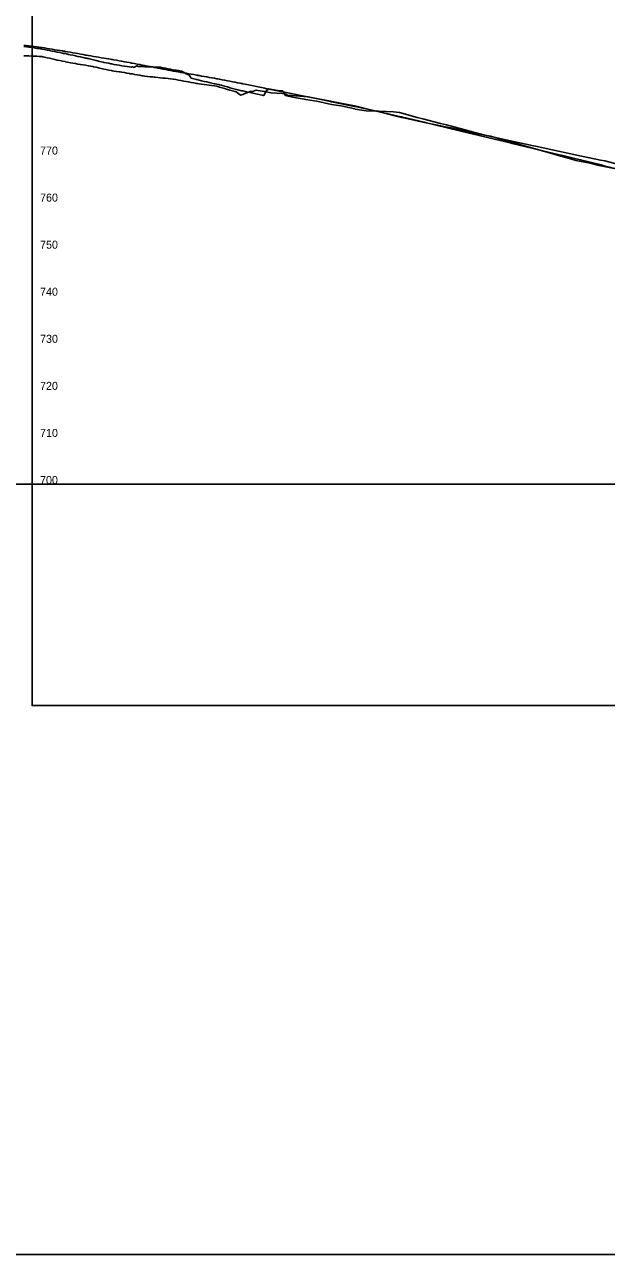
# Model space of a CAD drawing. Extents: x 1935020 to 1938620, y 1201670 to 1203870.
# Drawn here: x 1936228 to 1936846, y 1201670 to 1202977 of the extents above; entities that cross this region are included whole.
import ezdxf

# ---------------------------------------------------------------- set-up
doc = ezdxf.new("R2010")
doc.units = 0
for name, color, linetype in [('BR_EXIST_GROUND_LT', 7, 'Continuous'), ('BR_EXIST_GROUND_RT', 7, 'Continuous'), ('RD_DDB_ElevTX', 7, 'Continuous'), ('RD_DDB_Profile_EX', 7, 'Continuous'), ('RD_GPK_Profile_Cell', 7, 'Continuous'), ('RD_SHT_IplotShp', 7, 'Continuous'), ('RD_SHT_ShtClip', 7, 'Continuous')]:
    doc.layers.add(name, color=color, linetype=linetype)

msp = doc.modelspace()

# ---------------------------------------------------------------- linework, layer by layer
at = {"layer": 'BR_EXIST_GROUND_LT'}
msp.add_lwpolyline([(1936226.8, 1202943.8), (1936229.5, 1202943.7), (1936232.2, 1202943.5), (1936235, 1202943.4), (1936237.7, 1202943.3), (1936240.4, 1202943.2), (1936243.2, 1202943.1), (1936245.4, 1202943), (1936245.9, 1202942.9), (1936246.9, 1202942.7), (1936248.6, 1202942.3), (1936251.4, 1202941.6), (1936254.1, 1202941), (1936256.9, 1202940.4), (1936259.6, 1202939.8), (1936262.3, 1202939.2), (1936265.1, 1202938.6), (1936267.8, 1202938), (1936270.5, 1202937.5), (1936270.9, 1202937.4), (1936273.3, 1202936.9), (1936276.2, 1202936.3), (1936278.7, 1202935.9), (1936281.5, 1202935.4), (1936284.2, 1202934.9), (1936286.9, 1202934.4), (1936289.7, 1202934), (1936292.4, 1202933.6), (1936295.2, 1202933.1), (1936297.9, 1202932.6), (1936300.2, 1202932.2), (1936300.6, 1202932.1), (1936303.4, 1202931.5), (1936306.1, 1202930.8), (1936308.8, 1202930.2), (1936311.6, 1202929.6), (1936314.3, 1202929), (1936317, 1202928.5), (1936319.8, 1202927.9), (1936320.6, 1202927.7), (1936322.5, 1202927.5), (1936325.2, 1202927.1), (1936328, 1202926.7), (1936329.2, 1202926.6), (1936330.7, 1202926.3), (1936333.5, 1202925.8), (1936336.2, 1202925.3), (1936338.9, 1202924.8), (1936339.7, 1202924.7), (1936341.7, 1202924.4), (1936344.4, 1202923.9), (1936347.1, 1202923.4), (1936349.9, 1202923), (1936352.6, 1202922.5), (1936353.6, 1202922.3), (1936355.3, 1202922.1), (1936358.1, 1202921.8), (1936360.8, 1202921.5), (1936363.5, 1202921.2), (1936365.2, 1202921), (1936366.3, 1202920.9), (1936369, 1202920.7), (1936371.7, 1202920.4), (1936374.5, 1202920.1), (1936375.9, 1202920), (1936377.2, 1202919.9), (1936380, 1202919.5), (1936382.7, 1202919.2), (1936385.4, 1202918.9), (1936385.7, 1202918.9), (1936388.2, 1202918.4), (1936390.9, 1202917.9), (1936393.6, 1202917.4), (1936396.4, 1202916.9), (1936399.1, 1202916.4), (1936401.4, 1202916.1), (1936401.8, 1202916), (1936404.6, 1202915.4), (1936407.3, 1202914.9), (1936410, 1202914.4), (1936411.3, 1202914.1), (1936412.8, 1202913.9), (1936415.5, 1202913.5), (1936418.3, 1202913.2), (1936421, 1202912.8), (1936423.7, 1202912.5), (1936426, 1202912.2), (1936426.5, 1202912.1), (1936429.2, 1202911.7), (1936431.9, 1202911.3), (1936434.7, 1202910.4), (1936437.4, 1202909.6), (1936440.1, 1202908.8), (1936440.9, 1202908.5), (1936442.9, 1202908), (1936445.6, 1202907.3), (1936448.3, 1202906.6), (1936451.1, 1202905.9), (1936452.4, 1202905.5), (1936453.8, 1202904.4), (1936456.6, 1202902.1), (1936457, 1202901.7), (1936459.3, 1202902.6), (1936460.8, 1202903.2), (1936462, 1202903.7), (1936467.2, 1202905.8), (1936469.6, 1202905.8), (1936473.6, 1202907.2), (1936475.2, 1202906.9), (1936482.3, 1202905.6), (1936489.6, 1202904.3), (1936501.1, 1202903.6), (1936502.9, 1202903.4), (1936503.8, 1202903.2), (1936506.9, 1202902), (1936528.4, 1202900.1), (1936552.6, 1202895.5), (1936553.3, 1202895.3), (1936553.9, 1202895.3), (1936577.8, 1202890.7), (1936578.2, 1202890.6), (1936600.8, 1202884.9), (1936602.7, 1202884.4), (1936604, 1202884.2), (1936628, 1202878.2), (1936628.6, 1202878.1), (1936652.3, 1202872.9), (1936676.4, 1202867.7), (1936679, 1202867.2), (1936680.6, 1202867), (1936704.2, 1202861.9), (1936719.6, 1202858.5), (1936743.8, 1202853.3), (1936768.2, 1202848), (1936770.3, 1202847.6), (1936794.8, 1202842.3), (1936814.2, 1202838.1), (1936839.1, 1202832.9), (1936843.7, 1202832), (1936862.4, 1202827.2)], dxfattribs=at)
at = {"layer": 'BR_EXIST_GROUND_RT'}
msp.add_lwpolyline([(1936226.8, 1202953.5), (1936229.5, 1202953.1), (1936232.2, 1202952.8), (1936235, 1202952.4), (1936237.7, 1202952), (1936240.4, 1202951.6), (1936240.9, 1202951.6), (1936243.2, 1202951.3), (1936244.5, 1202951.1), (1936245.9, 1202950.8), (1936248.6, 1202950.3), (1936251.4, 1202949.8), (1936254.1, 1202949.2), (1936256.9, 1202948.7), (1936259.6, 1202948.2), (1936262.3, 1202947.6), (1936265.1, 1202947.1), (1936267.8, 1202946.5), (1936268.9, 1202946.3), (1936270.5, 1202946), (1936273.3, 1202945.4), (1936274.2, 1202945.2), (1936276, 1202944.8), (1936278.7, 1202944.3), (1936281.5, 1202943.7), (1936284.2, 1202943.1), (1936286.9, 1202942.5), (1936289.7, 1202941.9), (1936292.4, 1202941.3), (1936293.5, 1202941.1), (1936294.5, 1202940.9), (1936295.2, 1202940.7), (1936296.2, 1202940.5), (1936297.9, 1202940.1), (1936300.6, 1202939.4), (1936303.4, 1202938.7), (1936306.1, 1202938.1), (1936308.8, 1202937.4), (1936310.9, 1202936.8), (1936311.6, 1202936.7), (1936314.3, 1202936.2), (1936317, 1202935.7), (1936319, 1202935.3), (1936319.8, 1202935.1), (1936322.5, 1202934.6), (1936325.2, 1202934.2), (1936328, 1202933.7), (1936330.7, 1202933.2), (1936333.5, 1202932.8), (1936336.2, 1202932.4), (1936336.6, 1202932.3), (1936338.9, 1202932), (1936341, 1202931.7), (1936341.7, 1202931.9), (1936342.2, 1202932.1), (1936343.8, 1202931.3), (1936344.4, 1202931.7), (1936346.6, 1202933.2), (1936347.1, 1202933), (1936348.3, 1202932.4), (1936349.9, 1202932.4), (1936352.6, 1202932.3), (1936355.3, 1202932.1), (1936358.1, 1202932), (1936360.8, 1202931.9), (1936363.5, 1202931.8), (1936366.3, 1202931.7), (1936369, 1202931.6), (1936371.8, 1202931.5), (1936374.5, 1202931), (1936377.2, 1202930.4), (1936380, 1202929.9), (1936382.7, 1202929.4), (1936383.2, 1202929.3), (1936385.4, 1202928.9), (1936388.2, 1202928.5), (1936388.6, 1202928.4), (1936390.9, 1202928), (1936393.6, 1202927.5), (1936394.1, 1202927.4), (1936396.4, 1202926.2), (1936399.1, 1202924.7), (1936401, 1202923.7), (1936402.1, 1202924), (1936404.6, 1202919.9), (1936407.3, 1202919.2), (1936410, 1202918.5), (1936410.4, 1202918.4), (1936412.8, 1202917.8), (1936415.5, 1202917.1), (1936418.3, 1202916.5), (1936421, 1202915.9), (1936423.7, 1202915.2), (1936426.5, 1202914.6), (1936429.3, 1202914), (1936430, 1202913.9), (1936431.9, 1202913.5), (1936434, 1202913.1), (1936434.7, 1202912.9), (1936436.6, 1202912.4), (1936437.4, 1202912.2), (1936440.1, 1202911.4), (1936442.9, 1202910.6), (1936445.6, 1202909.8), (1936448.3, 1202909), (1936451.1, 1202908.3), (1936454, 1202907.5), (1936456.6, 1202906.9), (1936458.1, 1202906.6), (1936458.5, 1202906.5), (1936459.3, 1202906.4), (1936462, 1202905.8), (1936479.8, 1202901.9), (1936481.6, 1202901.5), (1936484.8, 1202907.1), (1936486.2, 1202907.9), (1936486.7, 1202908.6), (1936490.4, 1202907.9), (1936496.7, 1202907), (1936500.5, 1202906.6), (1936501, 1202906.5), (1936501.3, 1202906.3), (1936502.2, 1202905.6), (1936504.4, 1202901.6), (1936514.4, 1202899.3), (1936528.5, 1202896.9), (1936538.1, 1202895.4), (1936553.5, 1202892), (1936563.5, 1202890.4), (1936578.4, 1202887.2), (1936578.7, 1202887.1), (1936590.5, 1202885.3), (1936603.8, 1202884.8), (1936619.4, 1202884.2), (1936625.7, 1202883.5), (1936644.7, 1202878.2), (1936650.6, 1202876.9), (1936669.4, 1202871.7), (1936675.6, 1202870.4), (1936694, 1202865.3), (1936700.6, 1202863.8), (1936716.4, 1202859.5), (1936722.3, 1202858.2), (1936739.6, 1202853.5), (1936747.3, 1202851.2), (1936763.6, 1202846.7), (1936772.3, 1202844.2), (1936787.6, 1202840), (1936797.3, 1202837.1), (1936806.4, 1202834.6), (1936813.1, 1202832.6), (1936828.2, 1202829.6), (1936838, 1202827.2), (1936853.9, 1202824)], dxfattribs=at)
at = {"layer": 'RD_DDB_Profile_EX'}
msp.add_lwpolyline([(1936226.8, 1202954.8), (1936229.5, 1202954.5), (1936232.2, 1202954.2), (1936235, 1202953.8), (1936237.7, 1202953.5), (1936240.4, 1202953.1), (1936243.2, 1202952.8), (1936244.9, 1202952.6), (1936245.9, 1202952.4), (1936248.6, 1202952), (1936251.4, 1202951.5), (1936254.1, 1202951.1), (1936256.9, 1202950.7), (1936259.6, 1202950.2), (1936262.3, 1202949.8), (1936265.1, 1202949.3), (1936267.8, 1202948.8), (1936268.9, 1202948.7), (1936269.9, 1202948.5), (1936270.5, 1202948.4), (1936273.3, 1202947.9), (1936276, 1202947.4), (1936278.7, 1202947), (1936281.5, 1202946.5), (1936284.2, 1202946), (1936286.9, 1202945.5), (1936289.7, 1202945), (1936292.4, 1202944.5), (1936293.3, 1202944.3), (1936295.2, 1202944), (1936295.5, 1202944), (1936297.9, 1202943.6), (1936300.6, 1202943.1), (1936303.4, 1202942.7), (1936306.1, 1202942.2), (1936308.8, 1202941.7), (1936311.6, 1202941.3), (1936314.3, 1202940.8), (1936317, 1202940.3), (1936319.9, 1202939.8), (1936320.5, 1202939.7), (1936321, 1202939.6), (1936322.5, 1202939.4), (1936325.2, 1202938.9), (1936328, 1202938.4), (1936330.7, 1202937.9), (1936333.5, 1202937.4), (1936336.2, 1202936.9), (1936338.9, 1202936.4), (1936340.3, 1202936.1), (1936341.2, 1202936), (1936341.7, 1202935.9), (1936344.4, 1202935.4), (1936347.1, 1202934.9), (1936349.9, 1202934.4), (1936352.6, 1202933.9), (1936355.3, 1202933.3), (1936358.1, 1202932.8), (1936360.8, 1202932.3), (1936363.5, 1202931.8), (1936365.3, 1202931.4), (1936365.9, 1202931.3), (1936366.3, 1202931.2), (1936369, 1202930.7), (1936371.7, 1202930.2), (1936374.5, 1202929.6), (1936377.2, 1202929.1), (1936380, 1202928.5), (1936382.7, 1202928), (1936385.4, 1202927.4), (1936386.8, 1202927.2), (1936388.2, 1202926.9), (1936390.9, 1202926.5), (1936393.6, 1202926), (1936396.4, 1202925.5), (1936399.1, 1202925.1), (1936401.8, 1202924.6), (1936404.6, 1202924.1), (1936407.3, 1202923.7), (1936410, 1202923.2), (1936410.8, 1202923.1), (1936411.7, 1202922.9), (1936412.8, 1202922.7), (1936415.5, 1202922.2), (1936418.3, 1202921.7), (1936421, 1202921.3), (1936423.7, 1202920.8), (1936426.5, 1202920.3), (1936429.2, 1202919.8), (1936431.9, 1202919.3), (1936432.8, 1202919.1), (1936434.1, 1202918.9), (1936434.7, 1202918.8), (1936437.4, 1202918.3), (1936440.1, 1202917.7), (1936442.9, 1202917.2), (1936445.6, 1202916.7), (1936448.3, 1202916.1), (1936451.1, 1202915.6), (1936453.8, 1202915), (1936456.6, 1202914.5), (1936457.7, 1202914.3), (1936458.5, 1202914.1), (1936459.3, 1202913.9), (1936462, 1202913.4), (1936482.6, 1202909.3), (1936483.6, 1202909.1), (1936507.2, 1202904.3), (1936508.8, 1202904), (1936528.2, 1202900.1), (1936528.6, 1202900), (1936552.4, 1202895.2), (1936553.6, 1202894.9), (1936577.8, 1202890), (1936578.2, 1202889.9), (1936578.7, 1202889.8), (1936603.2, 1202884.4), (1936627.3, 1202879), (1936627.9, 1202878.9), (1936651.9, 1202873.1), (1936652.9, 1202872.9), (1936676.5, 1202867.1), (1936677.8, 1202866.8), (1936701.1, 1202861.2), (1936702.8, 1202860.8), (1936719.2, 1202856.9), (1936720.6, 1202856.6), (1936743.2, 1202851.1), (1936745.5, 1202850.6), (1936767.9, 1202845.2), (1936770.5, 1202844.6), (1936792.5, 1202839.3), (1936795.5, 1202838.6), (1936797.7, 1202838.1), (1936814.8, 1202834), (1936818.1, 1202833.2), (1936839.8, 1202827.7), (1936842.8, 1202826.9), (1936864.8, 1202821.4)], dxfattribs=at)
at = {"layer": 'RD_GPK_Profile_Cell'}
msp.add_line((1935783.9, 1202488.5), (1937855.4, 1202488.5), dxfattribs=at)
at = {"layer": 'RD_SHT_IplotShp'}
msp.add_lwpolyline([(1935019.6, 1201670.4), (1938619.6, 1201670.4), (1938619.6, 1203870.4), (1935019.6, 1203870.4)], close=True, dxfattribs=at)
at = {"layer": 'RD_SHT_ShtClip'}
msp.add_lwpolyline([(1936235.5, 1203353.5), (1938035.5, 1203353.5), (1938035.5, 1202253.5), (1936235.5, 1202253.5)], close=True, dxfattribs=at)

# ---------------------------------------------------------------- texts
at = {"layer": 'RD_DDB_ElevTX'}
for s, p in [('770', (1936244, 1202838.8)), ('760', (1936244, 1202788.8)), ('750', (1936244, 1202738.8)), ('740', (1936244, 1202688.8)), ('730', (1936244, 1202638.8)), ('720', (1936244, 1202588.8)), ('710', (1936244, 1202538.8)), ('700', (1936244, 1202488.8))]:
    msp.add_text(s, height=8.5, dxfattribs=at).set_placement(p)

doc.saveas('drawing.dxf')
